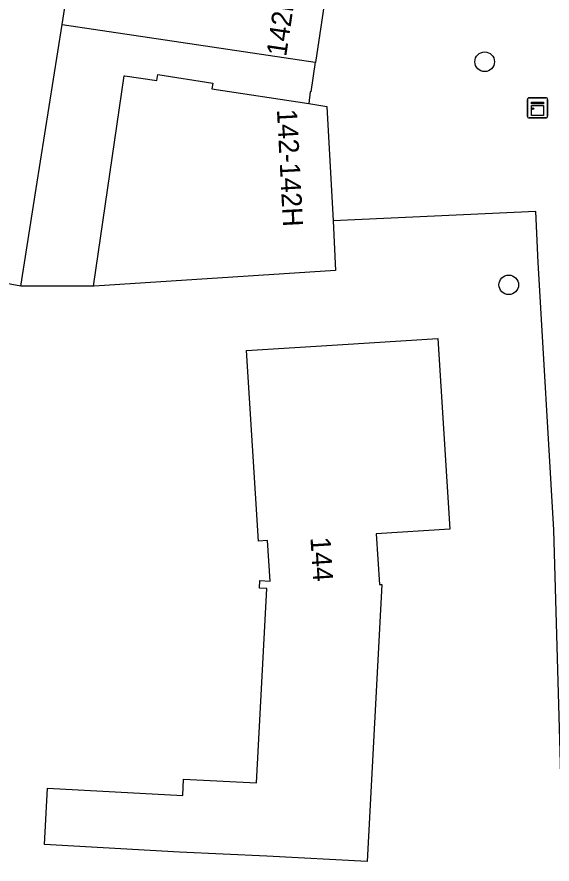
# Model space of a CAD drawing. Extents: x 162172 to 163187, y 382874 to 383684.
# Drawn here: x 163134.04 to 163160.7, y 383216.32 to 383258.55 of the extents above; entities that cross this region are included whole.
import ezdxf

# ---------------------------------------------------------------- set-up
doc = ezdxf.new("R2010")
doc.units = 0
for name, color, linetype in [('IMGEO_Boom', 7, 'Continuous'), ('IMGEO_Erf', 7, 'Continuous'), ('IMGEO_Kast', 7, 'Continuous'), ('IMGEO_Pand', 7, 'Continuous'), ('IMGEO_Pand_nummerreeks', 7, 'Continuous'), ('IMGEO_Voetpad_open', 7, 'Continuous')]:
    doc.layers.add(name, color=color, linetype=linetype)

msp = doc.modelspace()

# ---------------------------------------------------------------- linework, layer by layer
at = {"layer": 'IMGEO_Boom'}
for centre in [(163157.343, 383256.314), (163158.54, 383245.194)]:
    msp.add_circle(centre, 0.489, dxfattribs=at)
at = {"layer": 'IMGEO_Erf'}
msp.add_lwpolyline([(163137.847, 383245.119), (163134.239, 383245.124)], dxfattribs=at)
at = {"layer": 'IMGEO_Kast'}
for p, q in [((163159.474, 383253.59), (163159.474, 383254.431)), ((163159.474, 383254.431), (163159.474, 383253.59)), ((163159.549, 383254.515), (163160.39, 383254.515)), ((163160.39, 383254.515), (163159.549, 383254.515)), ((163160.474, 383254.44), (163160.474, 383253.599)), ((163160.474, 383253.599), (163160.474, 383254.44)), ((163160.399, 383253.515), (163159.558, 383253.515)), ((163159.558, 383253.515), (163160.399, 383253.515))]:
    msp.add_line(p, q, dxfattribs=at)
for points in [[(163159.669, 383254.305), (163160.269, 383254.305), (163160.269, 383254.22), (163159.669, 383254.22), (163159.669, 383254.305)], [(163159.669, 383254.13), (163160.269, 383254.13), (163160.269, 383253.641), (163159.669, 383253.641), (163159.669, 383254.13)]]:
    msp.add_lwpolyline(points, dxfattribs=at)
msp.add_circle((163159.753, 383253.979), 0.0377, dxfattribs=at)
for centre, start, end in [((163159.552, 383254.437), 92.4484, 184.2845), ((163159.552, 383254.437), 92.4484, 184.2845), ((163160.396, 383254.437), 2.4484, 94.2845), ((163160.396, 383254.437), 2.4484, 94.2845), ((163159.552, 383253.593), 182.4484, 274.2845), ((163159.552, 383253.593), 182.4484, 274.2845), ((163160.396, 383253.593), 272.4484, 4.2845), ((163160.396, 383253.593), 272.4484, 4.2845)]:
    msp.add_arc(centre, 0.0779, start, end, dxfattribs=at)
at = {"layer": 'IMGEO_Pand'}
for points in [[(163136.289, 383258.172), (163137.626, 383266.681)], [(163148.897, 383256.288), (163148.928, 383256.284), (163150.191, 383264.741)], [(163134.239, 383245.124), (163135.005, 383250), (163136.289, 383258.172)], [(163136.289, 383258.172), (163148.897, 383256.288)], [(163137.847, 383245.119), (163139.384, 383255.616), (163139.409, 383255.613), (163141.012, 383255.373), (163141.057, 383255.67), (163143.795, 383255.25), (163143.752, 383254.963), (163148.588, 383254.239)], [(163148.588, 383254.239), (163149.484, 383254.082), (163149.786, 383248.385)], [(163149.786, 383248.385), (163149.918, 383245.907), (163137.886, 383245.121), (163137.847, 383245.119)], [(163134.239, 383245.124), (163130.716, 383245.776)], [(163135.416, 383217.303), (163135.565, 383220.1), (163142.296, 383219.742), (163142.34, 383220.557), (163145.971, 383220.364), (163146.486, 383230.051), (163146.124, 383230.071), (163146.144, 383230.449), (163146.65, 383230.422), (163146.522, 383232.446), (163146.08, 383232.418), (163145.478, 383241.918), (163150.011, 383242.206), (163155, 383242.522), (163155.603, 383233.012), (163151.934, 383232.78), (163152.094, 383230.259), (163152.221, 383230.253), (163151.487, 383216.451), (163146.495, 383216.717), (163142.144, 383216.918), (163135.416, 383217.303)]]:
    msp.add_lwpolyline(points, dxfattribs=at)
at = {"layer": 'IMGEO_Voetpad_open'}
for points in [[(163148.897, 383256.288), (163148.674, 383254.811), (163148.649, 383254.815), (163148.588, 383254.239)], [(163150.387, 383109.402), (163154.256, 383131.058), (163157.499, 383151.959), (163158.378, 383158.574), (163159.977, 383173.635), (163161.497, 383190.557), (163161.526, 383207.385), (163160.795, 383232.984), (163160.002, 383246.311), (163159.893, 383248.853), (163149.786, 383248.385)]]:
    msp.add_lwpolyline(points, dxfattribs=at)

# ---------------------------------------------------------------- texts
at = {"layer": 'IMGEO_Pand_nummerreeks'}
for s, rotation, p in [('142D-142P', 81.5032, (163147.45, 383256.543)), ('142-142H', 273.0365, (163146.989, 383253.931)), ('144', 273.6315, (163148.659, 383232.596))]:
    msp.add_text(s, height=1, rotation=rotation, dxfattribs=at).set_placement(p)

doc.saveas('drawing.dxf')
